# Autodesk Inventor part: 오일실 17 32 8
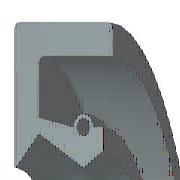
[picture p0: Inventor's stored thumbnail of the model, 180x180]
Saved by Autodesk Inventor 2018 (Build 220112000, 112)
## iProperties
IsCustomPart: 1
Created: 2012-02
Part Number: 오일실 17 32 8
Material: 고무
Description: 오일-실
Document SubType Name: Modeling
Standard: KS B 2804
Designer: mduedu
Standards Organization: KS
Language: ko-KR
Size Designation: D - 17 32 8
Categories: <MemberInstance><Categories><Category DisplayName="샤프트 부품" InternalName="7f7aeb1f-a693-4053-b835-cee3144e0d98" Mnemonic="SHFT"><Category DisplayName="실링" Intern
Density: 0.93 g/cm^3
Appearance: 고무 - 검은색 - 버전 1.1
Author: mduedu
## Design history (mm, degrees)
revolve "본체" stored, may be unused: angle "d17" = 90 deg
revolve "스프링1" stored, may be unused: angle "d18" = 90 deg
body "Solid1"
sketch "스케치1"
  geometry: L1 (0, 16)-(8, 16); L2 (8, 14.25)-(1.75, 14.25); L3 (1.75, 10.25)-(4.9, 8.5); L4 (4.9, 8.5)-(0, 8.5); L5 (0, 0)-(9.586, 0) reference; L6 (4.9, 8.5)-(6.3, 9.375); L7 (0, 18)-(0, -3) reference; L8 (-1.941, 0)-(11.507, 0) reference; L9 (4.2, 10.6)-(1.75, 11.21); L10 (1.75, 11.21)-(1.75, 14.25); L11 (0, 16)-(0, 8.588); L12 (4.9, 8.5)-(0, 8.5); L13 (1.75, 10.25)-(0.152, 8.528); L14 (8, 16)-(8, 14.25); L15 (5.6, 10.6)-(6.3, 10.6); L16 (6.3, 10.6)-(6.3, 9.375); C1 r 0.455 at (4.9, 10.6); A1 r 0.7 centre (4.9, 10.6) between (5.6, 10.6) and (4.2, 10.6); A2 r 0.088 centre (0.088, 8.588) between (0, 8.588) and (0.152, 8.528); 1 further point
  constraints: 28 end point, 5 horizontal alignment, 5 point on line, 4 point on circle, 4 vertical alignment, 3 centre point, 3 tangent, 2 collinear, 2 horizontal, 2 perpendicular, 1 coincident, 1 parallel
  dimensions: "d0" = 32 diameter of L1 L5 (= SD2); "d1" = 1.75 distance of L1.end L2.start (= SD); "d2" = 0.91 diameter of C1 (= SPDI); "d3" = 1.4 diameter of A1 (= SPDA); "d4" = 17 diameter of L3.end L5 (= NND); "d5" = 20.5 diameter of L3.start L5 (= TKDM); "d7" = 22.42 diameter of L9.end L5 (= TKDM + 0.24 x SWDT); "d8" = 1.75 distance between parallel lines of L11 L10 (= SD); "d9" = 4.9 distance from line of L11 C1.centre (= SPDST); "d10" = 21.2 diameter of C1.centre L5 (= HLDM); "d11" = 0.0875 radius of A2 (= 0.25 x LAB); "d12" = 6.3 distance between parallel lines of L11 L16 (= SDI); "d13" = 18.75 diameter of L6.end L5 (= ABDM); "d14" = 8 distance from line of L11 L1.end (= SWDT)
fillet "모깎기1" dims "d6" = 0.3 (= RR)
other parameters: "SD2" = 32 [user parameter; used in 1 equation term], "SWDT" = 8 [user parameter; used in 2 equation terms], "RR" = 0.3 [user parameter; used in 1 equation term], "SD" = 1.75 [user parameter; used in 2 equation terms], "NND" = 17 [user parameter; used in 1 equation term], "SPDA" = 1.4 [user parameter; used in 1 equation term], "SPDI" = 0.91 [user parameter; used in 1 equation term], "TKDM" = 20.5 [user parameter; used in 2 equation terms], "HLDM" = 21.2 [user parameter; used in 1 equation term], "ABDM" = 18.75 [user parameter; used in 1 equation term], "SDI" = 6.3 [user parameter; used in 1 equation term], "SPDST" = 4.9 [user parameter; used in 1 equation term], "LAB" = 0.35 [user parameter; used in 1 equation term], "d15" = 0, "d16" = 0, "d19" = 0
